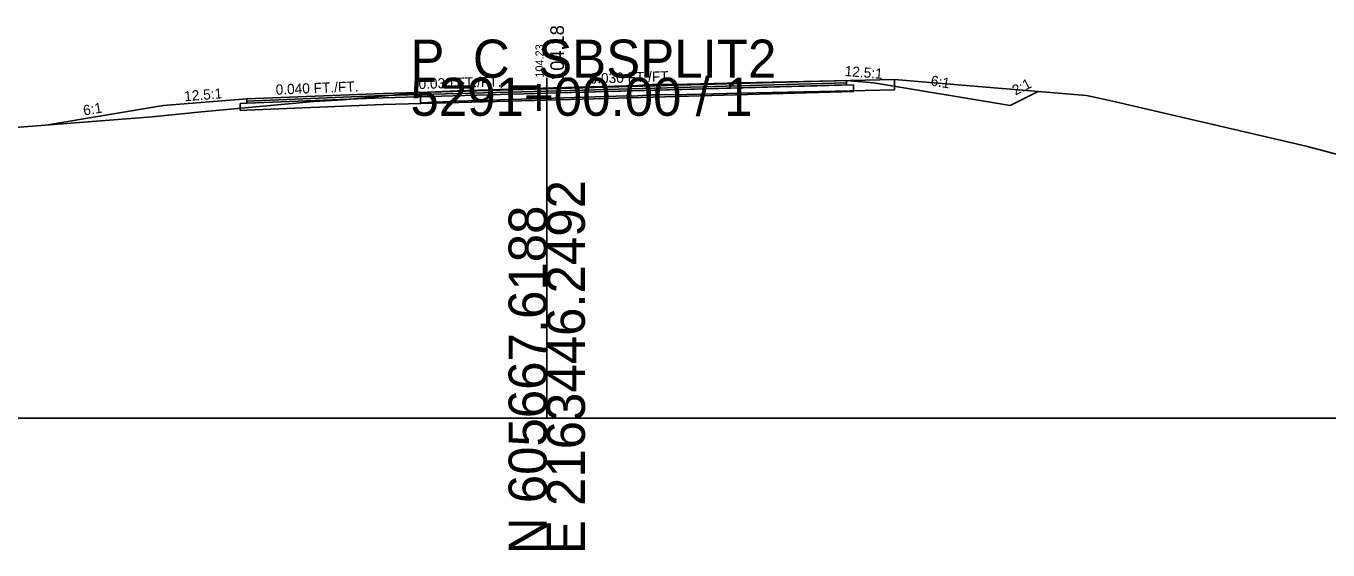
# Model space of a CAD drawing. Extents: x -26 to 1303, y -10 to 12033.
# Drawn here: x 111.8 to 207.3, y 5990.3 to 6028.8 of the extents above; entities that cross this region are included whole.
import ezdxf

# ---------------------------------------------------------------- set-up
doc = ezdxf.new("R2010")
doc.units = 0
for name, color, linetype in [('RD_GPK_XS_Cell', 7, 'Continuous'), ('RD_XS_Base', 7, 'Continuous'), ('RD_XS_ExGround', 7, 'Continuous'), ('RD_XS_ExPaveRet', 7, 'Continuous'), ('RD_XS_Greenside', 7, 'Continuous'), ('RD_XS_Pave', 7, 'Continuous'), ('RD_XS_PaveOvlay_CP', 7, 'Continuous'), ('RD_XS_TieSlope', 7, 'Continuous'), ('RD_XS_TX_Elev_EX', 7, 'Continuous'), ('RD_XS_TX_Elev_PR', 7, 'Continuous'), ('RD_XS_TX_ShdSlope', 7, 'Continuous'), ('RD_XS_TX_Slope', 7, 'Continuous')]:
    doc.layers.add(name, color=color, linetype=linetype)

msp = doc.modelspace()

# ---------------------------------------------------------------- linework, layer by layer
at = {"layer": 'RD_GPK_XS_Cell'}
for p, q in [((150, 6000), (150, 6025)), ((0, 6000), (150, 6000)), ((150, 6000), (300, 6000))]:
    msp.add_line(p, q, dxfattribs=at)
at = {"layer": 'RD_XS_Base'}
for p, q in [((150, 6023.86), (138, 6023.524)), ((150, 6023.86), (172, 6024.475)), ((150, 6023.36), (150, 6024.019)), ((150, 6024.019), (150, 6024.019)), ((150, 6024.019), (150, 6024.019)), ((150, 6024.019), (150, 6023.86)), ((172.5, 6023.989), (150, 6023.36)), ((150, 6023.86), (150, 6023.86)), ((150, 6023.36), (150, 6023.86)), ((150, 6023.86), (150, 6023.86)), ((150, 6023.86), (150, 6023.86)), ((162, 6024.196), (162, 6024.196)), ((162, 6024.196), (162, 6024.196)), ((162, 6023.696), (162, 6023.696)), ((162, 6023.696), (162, 6023.696)), ((172, 6024.476), (172, 6024.476)), ((172.5, 6024.489), (172.5, 6023.989)), ((172.5, 6024.456), (172.5, 6024.456)), ((128, 6023.124), (127.5, 6023.104)), ((127.5, 6023.104), (127.5, 6023.104)), ((127.5, 6023.104), (127.5, 6022.604)), ((138, 6023.524), (128, 6023.124)), ((128, 6023.124), (128, 6023.124)), ((128, 6022.624), (138, 6023.024)), ((136, 6023.444), (136, 6023.444)), ((136, 6022.944), (136, 6022.944)), ((138, 6023.024), (150, 6023.36)), ((150, 6023.36), (150, 6023.36)), ((127.5, 6022.604), (128, 6022.624)), ((128, 6022.624), (128, 6022.624))]:
    msp.add_line(p, q, dxfattribs=at)
at = {"layer": 'RD_XS_ExGround'}
msp.add_lwpolyline([(110.39, 6021.306), (121.046, 6022.13), (124.66, 6022.499), (132.919, 6023.259), (135.058, 6023.38), (140.743, 6023.905), (143.436, 6024.027), (150.487, 6024.248), (155.861, 6024.413), (156.316, 6024.404), (157.718, 6024.495), (158.216, 6024.501), (160.309, 6024.524), (164.221, 6024.614), (171.194, 6024.771), (175.503, 6024.865), (177.539, 6024.693), (189.596, 6023.703), (190.62, 6023.463), (191.724, 6023.23), (205.711, 6019.977), (211.443, 6018.444)], dxfattribs=at)
at = {"layer": 'RD_XS_ExPaveRet'}
for points in [[(175.502, 6024.865), (175.502, 6024.865), (175.502, 6024.115), (171.194, 6024.021), (171.194, 6024.021), (164.221, 6023.864), (160.309, 6023.774), (160.309, 6023.774), (158.216, 6023.751), (158.216, 6023.751), (157.718, 6023.745), (157.718, 6023.745), (156.316, 6023.654), (156.316, 6023.654), (155.861, 6023.663), (155.861, 6023.663), (155.861, 6023.663), (150.487, 6023.498), (150.487, 6023.498), (143.436, 6023.277), (143.436, 6023.277), (140.743, 6023.155), (140.743, 6023.905), (140.743, 6023.905), (143.436, 6024.027), (143.436, 6024.027), (150.487, 6024.248), (150.487, 6024.248), (155.861, 6024.414), (155.861, 6024.414), (155.861, 6024.414), (156.316, 6024.404), (156.316, 6024.404), (157.718, 6024.495), (157.718, 6024.495), (158.216, 6024.501), (158.216, 6024.501), (160.309, 6024.524), (160.309, 6024.524), (164.221, 6024.614), (171.194, 6024.771), (171.194, 6024.771), (175.502, 6024.865)], [(171.194, 6024.771), (164.221, 6024.614), (160.309, 6024.524), (158.216, 6024.501), (157.718, 6024.495), (156.316, 6024.404), (155.861, 6024.414), (150.487, 6024.248), (143.436, 6024.027), (140.743, 6023.905), (140.743, 6023.155), (143.436, 6023.277), (150.487, 6023.498), (155.861, 6023.663), (156.316, 6023.654), (157.718, 6023.745), (158.216, 6023.751), (160.309, 6023.774), (164.221, 6023.864), (171.194, 6024.021), (175.502, 6024.115), (175.502, 6024.865), (171.194, 6024.771)]]:
    msp.add_lwpolyline(points, dxfattribs=at)
at = {"layer": 'RD_XS_Greenside'}
for p, q in [((174, 6024.634), (184, 6022.967)), ((184, 6022.967), (186.054, 6023.994)), ((121.862, 6022.951), (113.386, 6021.538))]:
    msp.add_line(p, q, dxfattribs=at)
at = {"layer": 'RD_XS_Pave'}
for p, q in [((172, 6024.794), (150, 6024.178)), ((172, 6024.634), (150, 6024.019)), ((150, 6024.019), (172, 6024.634)), ((172, 6024.635), (172, 6024.794)), ((172, 6024.794), (172, 6024.794)), ((172, 6024.476), (172, 6024.635)), ((172, 6024.635), (172, 6024.635)), ((138, 6023.842), (128, 6023.442)), ((128, 6023.283), (138, 6023.683)), ((138, 6023.683), (128, 6023.283)), ((136, 6023.762), (136, 6023.762)), ((150, 6024.178), (138, 6023.842)), ((138, 6023.683), (150, 6024.019)), ((150, 6024.019), (138, 6023.683)), ((138, 6023.524), (150, 6023.86)), ((150, 6023.86), (172.5, 6024.489)), ((150, 6024.178), (150, 6024.178)), ((150, 6024.019), (150, 6024.019)), ((150, 6024.019), (150, 6024.019)), ((150, 6024.019), (150, 6023.86)), ((150, 6024.019), (150, 6024.019)), ((150, 6023.86), (150, 6024.019)), ((150, 6024.019), (150, 6024.019)), ((150, 6024.019), (150, 6024.019)), ((150, 6023.86), (150, 6023.86)), ((150, 6023.86), (150, 6023.86)), ((162, 6024.514), (162, 6024.514)), ((162, 6024.514), (162, 6024.514)), ((162, 6024.355), (162, 6024.355)), ((162, 6024.355), (162, 6024.355)), ((162, 6024.355), (162, 6024.355)), ((162, 6024.355), (162, 6024.355)), ((162, 6024.196), (162, 6024.196)), ((162, 6024.196), (162, 6024.196)), ((128, 6023.124), (138, 6023.524)), ((128, 6023.442), (128, 6023.442)), ((128, 6023.442), (128, 6023.283)), ((128, 6023.283), (128, 6023.283)), ((128, 6023.283), (128, 6023.124)), ((136, 6023.603), (136, 6023.603)), ((136, 6023.603), (136, 6023.603)), ((136, 6023.444), (136, 6023.444))]:
    msp.add_line(p, q, dxfattribs=at)
at = {"layer": 'RD_XS_PaveOvlay_CP'}
for p, q in [((172, 6024.794), (150, 6024.178)), ((138, 6023.842), (128, 6023.442)), ((136, 6023.762), (136, 6023.762)), ((150, 6024.178), (138, 6023.842)), ((150, 6024.178), (150, 6024.178)), ((162, 6024.514), (162, 6024.514)), ((162, 6024.514), (162, 6024.514))]:
    msp.add_line(p, q, dxfattribs=at)
at = {"layer": 'RD_XS_TieSlope'}
for p, q in [((172, 6024.794), (174, 6024.634)), ((128, 6023.442), (121.862, 6022.951))]:
    msp.add_line(p, q, dxfattribs=at)

# ---------------------------------------------------------------- texts
at = {"layer": 'RD_GPK_XS_Cell'}
for s, p in [('P_C_SBSPLIT2', (140, 6025)), ('5291+00.00 / 1', (140, 6022.2))]:
    msp.add_text(s, height=2.8, dxfattribs=at).set_placement(p)
for s, p in [('E 2163446.2492', (152.8, 5990)), ('N 605667.6188', (150, 5990))]:
    msp.add_text(s, height=2.8, rotation=90, dxfattribs=at).set_placement(p)
at = {"layer": 'RD_XS_TX_Elev_EX'}
msp.add_text('104.23', height=0.6, rotation=90, dxfattribs=at).set_placement((149.769, 6025.003))
at = {"layer": 'RD_XS_TX_Elev_PR'}
msp.add_text('104.18', height=1, rotation=90, dxfattribs=at).set_placement((151.262, 6024.768))
at = {"layer": 'RD_XS_TX_ShdSlope'}
for rotation, p in [(355.42608, (171.838, 6025.133)), (4.57392, (123.427, 6023.266))]:
    msp.add_text('12.5:1', height=0.75, rotation=rotation, dxfattribs=at).set_placement(p)
at = {"layer": 'RD_XS_TX_Slope'}
for s, rotation, p in [('0.040 FT./FT.', 2.29061, (130.125, 6023.753)), ('0.030 FT./FT.', 1.71836, (140.606, 6024.17)), ('0.030 FT./FT.', 1.71836, (153.155, 6024.564)), ('6:1', 350.53582, (178.131, 6024.441)), ('2:1', 26.56505, (184.383, 6023.69)), ('6:1', 9.46418, (116.051, 6022.217))]:
    msp.add_text(s, height=0.75, rotation=rotation, dxfattribs=at).set_placement(p)

doc.saveas('drawing.dxf')
